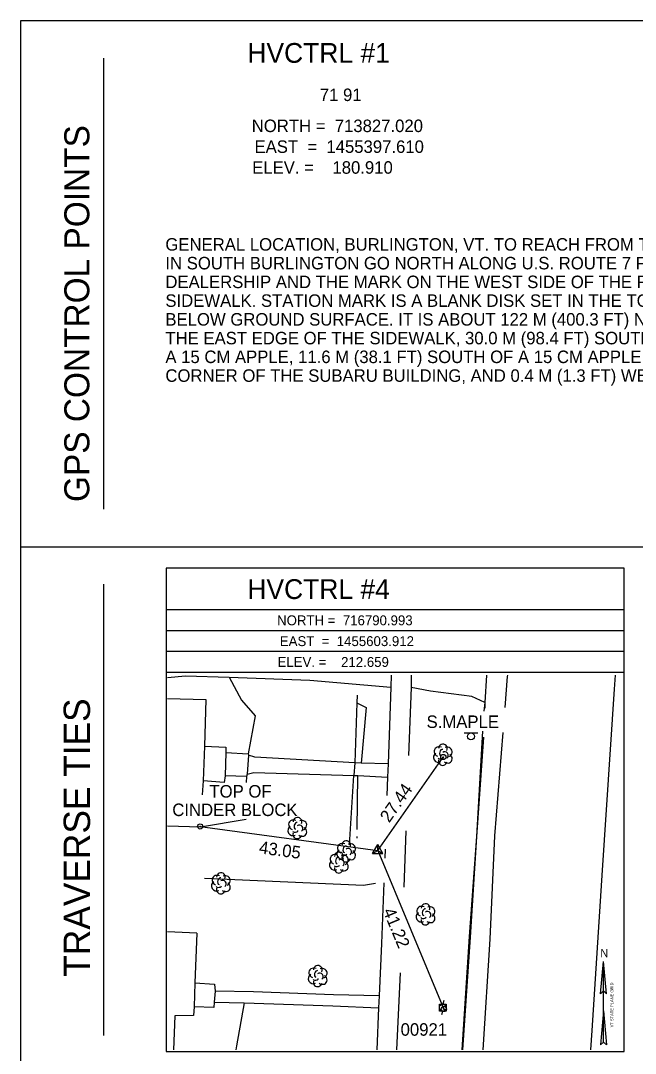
# Model space of a CAD drawing. Extents: x 1454512 to 1455152, y 715836 to 716256.
# Drawn here: x 1454512.2 to 1454659.9, y 716007.5 to 716255.5 of the extents above; entities that cross this region are included whole.
import ezdxf

# ---------------------------------------------------------------- set-up
doc = ezdxf.new("R2010")
doc.units = 0
for name, color, linetype in [('C_C', 7, 'Continuous'), ('CBP', 7, 'Continuous'), ('CPSM', 7, 'Continuous'), ('Default', 7, 'Continuous'), ('L_C', 7, 'Continuous'), ('LAHR', 7, 'Continuous'), ('LAPB', 7, 'Continuous'), ('LBC', 7, 'Continuous'), ('LBF', 7, 'Continuous'), ('LFNC', 7, 'Continuous'), ('LSH', 7, 'Continuous'), ('LTD', 7, 'Continuous'), ('NBL1', 7, 'Continuous'), ('NBL2', 7, 'Continuous'), ('NNA_P', 7, 'Continuous'), ('PET', 7, 'Continuous'), ('PSP', 7, 'Continuous'), ('RC', 7, 'Continuous'), ('RDP', 7, 'Continuous'), ('RSW', 7, 'Continuous'), ('SSGN', 7, 'Continuous'), ('U_C', 7, 'Continuous'), ('UP', 7, 'Continuous')]:
    doc.layers.add(name, color=color, linetype=linetype)

msp = doc.modelspace()

# ---------------------------------------------------------------- linework, layer by layer
at = {"layer": 'CBP'}
for centre, radius in [((1454613.71, 716078.69), 0.625), ((1454613.71, 716078.69), 0.0833), ((1454555.32, 716062.03), 0.625), ((1454555.32, 716062.03), 0.0833), ((1454613.86, 716018.18), 0.625), ((1454613.86, 716018.18), 0.0833)]:
    msp.add_circle(centre, radius, dxfattribs=at)
at = {"layer": 'CPSM'}
for p, q in [((1454596.72, 716055.49), (1454597.97, 716057.66)), ((1454599.22, 716055.49), (1454597.97, 716057.66)), ((1454597.97, 716056.21), (1454597.97, 716057.66)), ((1454596.72, 716055.49), (1454597.97, 716056.21)), ((1454596.72, 716055.49), (1454599.22, 716055.49)), ((1454597.97, 716056.21), (1454597.97, 716056.21)), ((1454597.97, 716056.21), (1454599.22, 716055.49))]:
    msp.add_line(p, q, dxfattribs=at)
at = {"layer": 'Default'}
for p, q in [((1454597.97, 716056.21), (1454613.71, 716078.69)), ((1454555.32, 716062.03), (1454597.97, 716056.21)), ((1454597.97, 716056.21), (1454613.86, 716018.18))]:
    msp.add_line(p, q, dxfattribs=at)
at = {"layer": 'LAHR'}
msp.add_lwpolyline([(1454556.34, 716049.62), (1454594.53, 716047.91), (1454597.44, 716048.43)], dxfattribs=at)
at = {"layer": 'LAPB'}
for points in [[(1454562.29, 716097.89), (1454565.26, 716092.31), (1454568.53, 716088.57), (1454566.79, 716079.5)], [(1454592.97, 716091.69), (1454595.16, 716090.55), (1454593.98, 716077.24)], [(1454566.39, 716074.03), (1454566.38, 716072.57)], [(1454593.02, 716061.32), (1454593.16, 716074.28)], [(1454566.34, 716063.72), (1454555.35, 716061.84)], [(1454593, 716059.19), (1454593.01, 716059.62)], [(1454565.86, 716019.69), (1454564.01, 716009.37), (1454563.83, 716008.41)]]:
    msp.add_lwpolyline(points, dxfattribs=at)
at = {"layer": 'LBC'}
for points in [[(1454547.47, 716092.78), (1454556.65, 716092.47), (1454556.32, 716081.3), (1454556, 716072.99), (1454555.8, 716069.62)], [(1454555.35, 716061.84), (1454547.47, 716062.09)], [(1454554.51, 716036.41), (1454547.47, 716036.7)], [(1454554.51, 716036.41), (1454554.04, 716024.49), (1454553.85, 716018.71), (1454553.66, 716016.6), (1454549.24, 716016.55), (1454548.88, 716008.41)]]:
    msp.add_lwpolyline(points, dxfattribs=at)
at = {"layer": 'LBF'}
for points in [[(1454556.32, 716081.3), (1454561.46, 716081.08), (1454561.43, 716079.75), (1454561.27, 716074.21), (1454561.1, 716072.6), (1454556, 716072.99)], [(1454561.43, 716079.75), (1454566.79, 716079.5), (1454566.9, 716079.11), (1454566.58, 716074.57), (1454566.39, 716074.03), (1454561.27, 716074.21)], [(1454554.04, 716024.49), (1454558.71, 716024.16), (1454558.94, 716022.48), (1454558.63, 716019.84), (1454558.58, 716018.55), (1454553.85, 716018.71)]]:
    msp.add_lwpolyline(points, dxfattribs=at)
at = {"layer": 'LFNC'}
for points in [[(1454592.98, 716093.52), (1454592.97, 716091.69), (1454592.49, 716077.29)], [(1454591.17, 716057.62), (1454592.2, 716074.24)]]:
    msp.add_lwpolyline(points, dxfattribs=at)
at = {"layer": 'LSH'}
for p, q in [((1454590.35, 716056.08), (1454590.35, 716056.08)), ((1454590.35, 716056.08), (1454590.35, 716056.08)), ((1454588.6, 716053.41), (1454588.6, 716053.41)), ((1454588.6, 716053.41), (1454588.6, 716053.41))]:
    msp.add_line(p, q, dxfattribs=at)
for centre in [(1454590.4, 716057.51), (1454588.65, 716054.84)]:
    msp.add_arc(centre, 1.05, 335.5272, 180.9563, dxfattribs=at)
for centre, major_axis, ratio, start_param, end_param in [((1454589.27, 716055.37), (0.58, -1.04), 0.959034, 3.141593, 6.283185), ((1454589.56, 716056.74), (1.21, -0.51), 0.895232, 1.570796, 4.712389), ((1454590.15, 716056.54), (-0.208, -0.792), 0.645439, 3.141593, 6.283185), ((1454590.85, 716055.91), (-0.5, 0.667), 0.989748, 3.141593, 6.283185), ((1454591.4, 716056.66), (-1.14, -0.48), 0.949671, 1.570796, 4.712389), ((1454587.81, 716054.08), (1.21, -0.51), 0.895232, 1.570796, 4.712389), ((1454588.39, 716053.87), (-0.208, -0.792), 0.645439, 3.141593, 6.283185), ((1454589.1, 716053.24), (-0.5, 0.667), 0.989748, 3.141593, 6.283185), ((1454589.64, 716053.99), (-1.14, -0.48), 0.949671, 1.570796, 4.712389), ((1454590.35, 716054.58), (0.26, 1.06), 0.942809, 1.570796, 4.712389), ((1454589.9, 716055.33), (-0.625, -0.083), 0.423636, 0, 3.141593), ((1454591.35, 716055.24), (-1.09, 0.79), 0.841452, 1.570796, 4.712389), ((1454587.52, 716052.7), (0.58, -1.04), 0.959034, 3.141593, 6.283185), ((1454588.6, 716051.91), (0.26, 1.06), 0.942809, 1.570796, 4.712389), ((1454588.14, 716052.66), (-0.625, -0.083), 0.423636, 0, 3.141593), ((1454589.6, 716052.58), (-1.09, 0.79), 0.841452, 1.570796, 4.712389)]:
    msp.add_ellipse(centre, major_axis=major_axis, ratio=ratio, start_param=start_param, end_param=end_param, dxfattribs=at)
at = {"layer": 'LTD'}
for p, q in [((1454613.58, 716079.28), (1454613.58, 716079.28)), ((1454613.58, 716079.28), (1454613.58, 716079.28)), ((1454578.63, 716061.7), (1454578.63, 716061.7)), ((1454578.63, 716061.7), (1454578.63, 716061.7)), ((1454560.25, 716048.42), (1454560.25, 716048.42)), ((1454560.25, 716048.42), (1454560.25, 716048.42)), ((1454609.42, 716040.97), (1454609.42, 716040.97)), ((1454609.42, 716040.97), (1454609.42, 716040.97)), ((1454583.52, 716026.15), (1454583.52, 716026.15)), ((1454583.52, 716026.15), (1454583.52, 716026.15))]:
    msp.add_line(p, q, dxfattribs=at)
for centre in [(1454613.63, 716080.72), (1454578.67, 716063.14), (1454560.3, 716049.86), (1454609.47, 716042.41), (1454583.56, 716027.58)]:
    msp.add_arc(centre, 1.05, 335.5272, 180.9563, dxfattribs=at)
for centre, major_axis, ratio, start_param, end_param in [((1454612.79, 716079.95), (1.21, -0.51), 0.895232, 1.570796, 4.712389), ((1454614.62, 716079.87), (-1.14, -0.48), 0.949671, 1.570796, 4.712389), ((1454612.5, 716078.57), (0.58, -1.04), 0.959034, 3.141593, 6.283185), ((1454613.37, 716079.74), (-0.208, -0.792), 0.645439, 3.141593, 6.283185), ((1454614.08, 716079.11), (-0.5, 0.667), 0.989748, 3.141593, 6.283185), ((1454614.58, 716078.45), (-1.09, 0.79), 0.841452, 1.570796, 4.712389), ((1454613.58, 716077.78), (0.26, 1.06), 0.942809, 1.570796, 4.712389), ((1454613.12, 716078.53), (-0.625, -0.083), 0.423636, 0, 3.141593), ((1454577.54, 716060.99), (0.58, -1.04), 0.959034, 3.141593, 6.283185), ((1454577.84, 716062.37), (1.21, -0.51), 0.895232, 1.570796, 4.712389), ((1454578.42, 716062.16), (-0.208, -0.792), 0.645439, 3.141593, 6.283185), ((1454579.13, 716061.54), (-0.5, 0.667), 0.989748, 3.141593, 6.283185), ((1454579.63, 716060.87), (-1.09, 0.79), 0.841452, 1.570796, 4.712389), ((1454579.67, 716062.29), (-1.14, -0.48), 0.949671, 1.570796, 4.712389), ((1454578.63, 716060.2), (0.26, 1.06), 0.942809, 1.570796, 4.712389), ((1454578.17, 716060.95), (-0.625, -0.083), 0.423636, 0, 3.141593), ((1454559.46, 716049.09), (1.21, -0.51), 0.895232, 1.570796, 4.712389), ((1454560.04, 716048.88), (-0.208, -0.792), 0.645439, 3.141593, 6.283185), ((1454560.75, 716048.26), (-0.5, 0.667), 0.989748, 3.141593, 6.283185), ((1454561.29, 716049.01), (-1.14, -0.48), 0.949671, 1.570796, 4.712389), ((1454559.17, 716047.71), (0.58, -1.04), 0.959034, 3.141593, 6.283185), ((1454560.25, 716046.92), (0.26, 1.06), 0.942809, 1.570796, 4.712389), ((1454559.79, 716047.67), (-0.625, -0.083), 0.423636, 0, 3.141593), ((1454561.25, 716047.59), (-1.09, 0.79), 0.841452, 1.570796, 4.712389), ((1454608.63, 716041.64), (1.21, -0.51), 0.895232, 1.570796, 4.712389), ((1454609.22, 716041.43), (-0.208, -0.792), 0.645439, 3.141593, 6.283185), ((1454609.92, 716040.81), (-0.5, 0.667), 0.989748, 3.141593, 6.283185), ((1454610.47, 716041.56), (-1.14, -0.48), 0.949671, 1.570796, 4.712389), ((1454608.34, 716040.27), (0.58, -1.04), 0.959034, 3.141593, 6.283185), ((1454609.43, 716039.47), (0.26, 1.06), 0.942809, 1.570796, 4.712389), ((1454608.97, 716040.22), (-0.625, -0.083), 0.423636, 0, 3.141593), ((1454610.43, 716040.14), (-1.09, 0.79), 0.841452, 1.570796, 4.712389), ((1454582.72, 716026.82), (1.21, -0.51), 0.895232, 1.570796, 4.712389), ((1454583.31, 716026.61), (-0.208, -0.792), 0.645439, 3.141593, 6.283185), ((1454584.02, 716025.98), (-0.5, 0.667), 0.989748, 3.141593, 6.283185), ((1454584.56, 716026.73), (-1.14, -0.48), 0.949671, 1.570796, 4.712389), ((1454582.43, 716025.44), (0.58, -1.04), 0.959034, 3.141593, 6.283185), ((1454583.52, 716024.65), (0.26, 1.06), 0.942809, 1.570796, 4.712389), ((1454583.06, 716025.4), (-0.625, -0.083), 0.423636, 0, 3.141593), ((1454584.52, 716025.32), (-1.09, 0.79), 0.841452, 1.570796, 4.712389)]:
    msp.add_ellipse(centre, major_axis=major_axis, ratio=ratio, start_param=start_param, end_param=end_param, dxfattribs=at)
at = {"layer": 'NBL1'}
msp.add_lwpolyline([(1454512.16, 715835.51), (1455152.16, 715835.51), (1455152.16, 716255.51), (1454512.16, 716255.51)], close=True, dxfattribs=at)
at = {"layer": 'NBL2'}
for p, q in [((1454532.16, 716138.18), (1454532.16, 716246.51)), ((1454512.16, 716129.18), (1455152.16, 716129.18)), ((1454532.16, 716011.85), (1454532.16, 716120.18)), ((1454657.16, 716114.01), (1454547.16, 716114.01)), ((1454657.16, 716109.01), (1454547.16, 716109.01)), ((1454657.16, 716104.01), (1454547.16, 716104.01)), ((1454657.16, 716099.01), (1454547.16, 716099.01))]:
    msp.add_line(p, q, dxfattribs=at)
msp.add_lwpolyline([(1454547.16, 716008.01), (1454657.16, 716008.01), (1454657.16, 716124.01), (1454547.16, 716124.01)], close=True, dxfattribs=at)
at = {"layer": 'NNA_P'}
for p, q in [((1454651.51, 716021.8), (1454652.21, 716029.6)), ((1454652.21, 716010.22), (1454652.21, 716029.6)), ((1454652.9, 716021.8), (1454652.21, 716029.6)), ((1454651.51, 716021.8), (1454652.21, 716022.57)), ((1454652.9, 716021.8), (1454652.21, 716022.57)), ((1454652.21, 716017.75), (1454651.49, 716009.58)), ((1454652.21, 716017.75), (1454652.93, 716009.58)), ((1454652.21, 716010.22), (1454651.49, 716009.58)), ((1454652.21, 716010.22), (1454652.93, 716009.58))]:
    msp.add_line(p, q, dxfattribs=at)
at = {"layer": 'PET'}
for points in [[(1454629.11, 716098.39), (1454629.09, 716098.03), (1454628.5, 716090.61)], [(1454649.19, 716008.41), (1454649.52, 716012.99), (1454651.98, 716051.56), (1454654.86, 716095), (1454655.11, 716098.39)], [(1454628.02, 716084.57), (1454626.05, 716059.77), (1454624.87, 716034.92), (1454623.18, 716008.41)]]:
    msp.add_lwpolyline(points, dxfattribs=at)
at = {"layer": 'PSP'}
for points in [[(1454624.11, 716098.39), (1454623.67, 716091.81), (1454623.7, 716090.45)], [(1454623.34, 716083.5), (1454621.7, 716059.51), (1454620.2, 716035.43), (1454618.34, 716008.41)]]:
    msp.add_lwpolyline(points, dxfattribs=at)
at = {"layer": 'RC'}
for points in [[(1454623.67, 716091.81), (1454623.48, 716089.74)], [(1454623.17, 716084.89), (1454621.66, 716059.58), (1454619.96, 716035.57), (1454618.16, 716008.41)]]:
    msp.add_lwpolyline(points, dxfattribs=at)
at = {"layer": 'RDP'}
for points in [[(1454547.47, 716097.75), (1454551.74, 716098.21), (1454562.29, 716097.89), (1454581.65, 716097.16), (1454601.11, 716095.45)], [(1454623.67, 716091.81), (1454620.54, 716093.19), (1454610.63, 716094.49), (1454605.99, 716095.36)]]:
    msp.add_lwpolyline(points, dxfattribs=at)
at = {"layer": 'RSW'}
for points in [[(1454601.2, 716098.39), (1454601.11, 716095.45), (1454600.48, 716077.02), (1454600.27, 716073.82), (1454600.16, 716069.43)], [(1454606.03, 716098.39), (1454605.99, 716095.36), (1454605.37, 716079.08)], [(1454592.49, 716077.29), (1454568.47, 716078.62), (1454566.9, 716079.11)], [(1454600.48, 716077.02), (1454593.98, 716077.24), (1454592.49, 716077.29), (1454592.2, 716074.24), (1454593.16, 716074.28), (1454600.27, 716073.82)], [(1454566.58, 716074.57), (1454568.19, 716074.99), (1454592.2, 716074.24)], [(1454604.69, 716060.99), (1454604.2, 716047.42)], [(1454599.77, 716056.57), (1454599.69, 716054.39)], [(1454599.46, 716048.46), (1454598.9, 716033.88), (1454598.27, 716021.36), (1454598.13, 716018.48), (1454597.78, 716008.41)], [(1454603.37, 716026.86), (1454602.48, 716008.41)], [(1454598.27, 716021.36), (1454587.33, 716021.63), (1454568.1, 716022.35), (1454558.94, 716022.48)], [(1454558.63, 716019.84), (1454565.86, 716019.69), (1454587.17, 716018.95), (1454598.13, 716018.48)]]:
    msp.add_lwpolyline(points, dxfattribs=at)
at = {"layer": 'SSGN'}
for p, q in [((1454618.72, 716084.47), (1454622.05, 716084.47)), ((1454620.37, 716083.64), (1454620.37, 716083.64))]:
    msp.add_line(p, q, dxfattribs=at)
msp.add_circle((1454620.37, 716083.64), 0.833, dxfattribs=at)
at = {"layer": 'UP'}
for p, q in [((1454612.77, 716017.7), (1454612.77, 716019.37)), ((1454612.77, 716019.37), (1454614.43, 716019.37)), ((1454613.85, 716020.2), (1454613.6, 716019.37)), ((1454614.43, 716019.37), (1454614.43, 716017.7)), ((1454614.43, 716017.7), (1454612.77, 716017.7)), ((1454613.35, 716016.87), (1454613.6, 716017.7)), ((1454613.6, 716018.54), (1454613.6, 716018.54))]:
    msp.add_line(p, q, dxfattribs=at)
msp.add_circle((1454613.6, 716018.54), 0.833, dxfattribs=at)

# ---------------------------------------------------------------- texts
at = {"layer": 'C_C'}
for s, p in [('TOP OF', (1454557.52, 716068.96)), ('CINDER BLOCK', (1454548.6, 716064.52))]:
    msp.add_text(s, height=3, dxfattribs=at).set_placement(p)
at = {"layer": 'Default'}
for s, p in [('GENERAL LOCATION, BURLINGTON, VT. TO REACH FROM THE U.S. ROUTE 7 (SHELBURNE ROAD) BRIDGE OVER I-189 ', (1454546.94, 716200.29)), ('IN SOUTH BURLINGTON GO NORTH ALONG U.S. ROUTE 7 FOR 0.55 MI (0.89 KM) TO THE BURLINGTON SUBARU ', (1454546.94, 716195.79)), ('DEALERSHIP AND THE MARK ON THE WEST SIDE OF THE ROAD IN A GRASS STRIP BETWEEN THE ROAD AND ', (1454546.94, 716191.29)), ('SIDEWALK. STATION MARK IS A BLANK DISK SET IN THE TOP OF A 20 CM DIAMETER CONCRETE MONUMENT 30 CM ', (1454546.94, 716186.79)), ('BELOW GROUND SURFACE. IT IS ABOUT 122 M (400.3 FT) NORTH OF FLYNN AVENUE, 1.6 M (5.2 FT) EAST OF ', (1454546.94, 716182.29)), ('THE EAST EDGE OF THE SIDEWALK, 30.0 M (98.4 FT) SOUTH OF GUY POLE NO.027, 7.6 M (24.9 FT) NORTH OF ', (1454546.94, 716177.79)), ('A 15 CM APPLE, 11.6 M (38.1 FT) SOUTH OF A 15 CM APPLE, 20.6 M (67.6 FT) NORTHEAST OF THE SOUTHEAST ', (1454546.94, 716173.29)), ('CORNER OF THE SUBARU BUILDING, AND 0.4 M (1.3 FT) WEST OF THE WEST CURB OF U.S. ROUTE 7. ', (1454546.94, 716168.79))]:
    msp.add_text(s, height=3, dxfattribs=at).set_placement(p)
for s, rotation, p in [('27.44', 54.9923, (1454600.72, 716062.75)), ('43.05', 352.2323, (1454569.31, 716055.58)), ('41.22', 292.6767, (1454599.15, 716041.73))]:
    msp.add_text(s, height=3, rotation=rotation, dxfattribs=at).set_placement(p)
at = {"layer": 'L_C'}
msp.add_text('S.MAPLE', height=3, dxfattribs=at).set_placement((1454609.7, 716085.67))
at = {"layer": 'NBL2'}
for s, height, p in [('     HVCTRL #1     ', 4.75, (1454557.81, 716245.39)), ('    71 91   ', 3, (1454579.59, 716236.21)), ('NORTH =  713827.020 ', 3, (1454567.69, 716228.76)), ('EAST  =  1455397.610', 3, (1454568.35, 716223.76)), ('ELEV. =    180.910  ', 3, (1454567.79, 716218.76)), ('     HVCTRL #4     ', 4.75, (1454557.81, 716116.64)), ('NORTH =  716790.993 ', 2.375, (1454573.78, 716110.33)), ('EAST  =  1455603.912', 2.375, (1454574.44, 716105.33)), ('ELEV. =    212.659  ', 2.375, (1454573.89, 716100.33))]:
    msp.add_text(s, height=height, dxfattribs=at).set_placement(p)
for s, height, p in [('GPS CONTROL POINTS', 6, (1454528.66, 716139.93)), ('TRAVERSE TIES', 6.3332, (1454528.83, 716025.95))]:
    msp.add_text(s, height=height, rotation=90, dxfattribs=at).set_placement(p)
at = {"layer": 'NNA_P'}
msp.add_text('N', height=1.97, dxfattribs=at).set_placement((1454651.45, 716030.61))
msp.add_text('VT STATE PLANE GRID', height=0.7, rotation=90.0204, dxfattribs=at).set_placement((1454654.56, 716013.79))
at = {"layer": 'U_C'}
msp.add_text('00921', height=3, dxfattribs=at).set_placement((1454603.46, 716011.77))

doc.saveas('drawing.dxf')
